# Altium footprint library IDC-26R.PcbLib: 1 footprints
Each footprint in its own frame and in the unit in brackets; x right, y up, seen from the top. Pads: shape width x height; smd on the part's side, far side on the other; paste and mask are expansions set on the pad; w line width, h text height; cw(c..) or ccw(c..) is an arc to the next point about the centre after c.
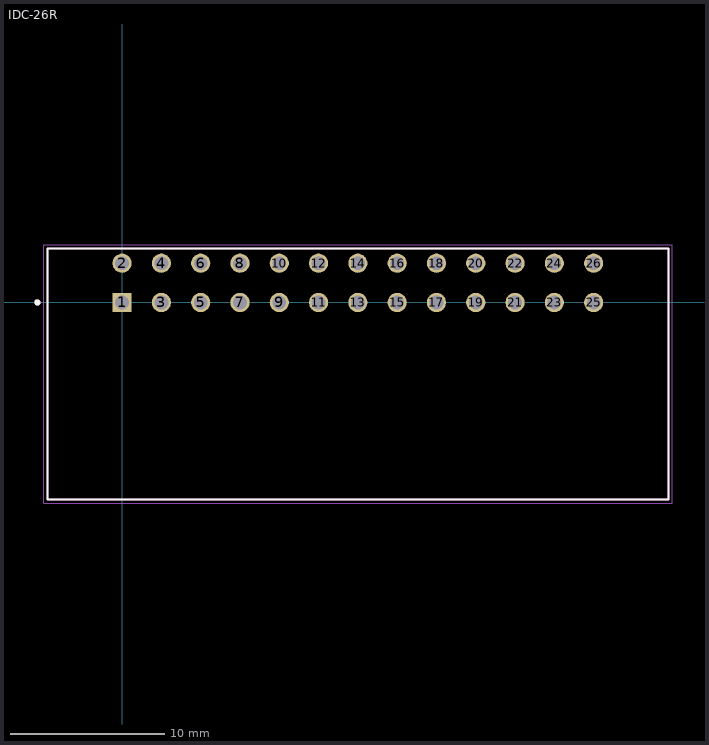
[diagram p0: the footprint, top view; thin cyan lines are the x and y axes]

## IDC-26R [mm]
pads (26):
  rect 1.24x1.24 hole 0.89: 1(0,0)
  round 1.24 hole 0.89: 2(0,2.54) 3(2.54,0) 4(2.54,2.54) 5(5.08,0) 6(5.08,2.54) 7(7.62,0) 8(7.62,2.54) 9(10.16,0) 10(10.16,2.54) 11(12.7,0) 12(12.7,2.54) 13(15.24,0) 14(15.24,2.54) 15(17.78,0) 16(17.78,2.54) 17(20.32,0) 18(20.32,2.54) 19(22.86,0) 20(22.86,2.54) 21(25.4,0) 22(25.4,2.54) 23(27.94,0) 24(27.94,2.54) 25(30.48,0) 26(30.48,2.54)
Top Overlay:
  circle w0.2: c-5.476,0 r0.1
  lines w0.127: -4.826,-12.738 -4.826,3.493 35.306,3.493 35.306,-12.738 -4.826,-12.738
Mechanical 13:
  circle w0.2: c-5.476,0 r0.1
  lines w0.127: -4.826,-12.738 -4.826,3.493 35.306,3.493 35.306,-12.738 ; -4.826,-12.738 35.306,-12.738 ; -4.826,-12.738 35.306,-12.738
Mechanical 15:
  lines w0.05: -5.076,-12.988 -5.076,3.743 35.556,3.743 35.556,-12.988 -5.076,-12.988
3D body "IDC-26R.STEP": height 10.13, standoff -3.78, extent -4.953,-12.827 35.179,3.404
